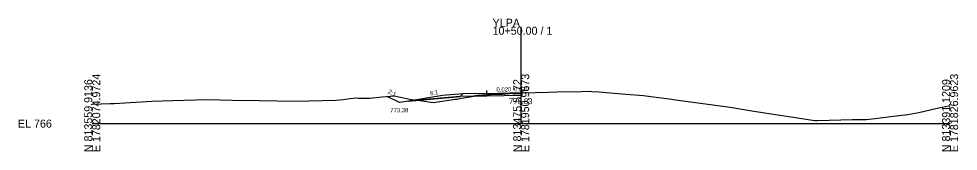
# Model space of a CAD drawing. Extents: x -76 to 1303, y -10 to 9544.
# Drawn here: x -25.7 to 302.8, y 490.3 to 536.8 of the extents above; entities that cross this region are included whole.
import ezdxf

# ---------------------------------------------------------------- set-up
doc = ezdxf.new("R2010")
doc.units = 0
for name, color, linetype in [('Exist Cross Section Cell', 7, 'Continuous'), ('Exist XS Center Line Elevation Label', 7, 'Continuous'), ('Exist XS Ground Line', 7, 'Continuous'), ('Prop XS Ditch Slope Text', 7, 'Continuous'), ('Prop XS Ditch Standard Text', 7, 'Continuous'), ('Prop XS Dump Level', 7, 'Continuous'), ('Prop XS Earthwork Shape', 7, 'Continuous'), ('Prop XS EOT Tick Mark', 7, 'Continuous'), ('Prop XS Finish Grade', 7, 'Continuous'), ('Prop XS Finish Grade Earthwork', 7, 'Continuous'), ('Prop XS Finish Grade Paved Shoulder', 7, 'Continuous'), ('Prop XS Finish Grade Pavement', 7, 'Continuous'), ('Prop XS Pvmt Edge Slope', 7, 'Continuous'), ('Prop XS SE Text', 7, 'Continuous'), ('Prop XS Side Slope Text', 7, 'Continuous'), ('Prop XS Subgrade Earthwork', 7, 'Continuous'), ('Scratch_Level_3', 7, 'Continuous')]:
    doc.layers.add(name, color=color, linetype=linetype)

msp = doc.modelspace()

# ---------------------------------------------------------------- linework, layer by layer
at = {"layer": 'Exist Cross Section Cell'}
for p, q in [((150, 500), (150, 533.98)), ((0, 500), (150, 500)), ((150, 500), (300, 500))]:
    msp.add_line(p, q, dxfattribs=at)
at = {"layer": 'Exist XS Ground Line'}
for p, q in [((97.02, 508.88), (101.39, 509.38)), ((101.39, 509.38), (105.59, 509.74)), ((105.59, 509.74), (110.49, 508.74)), ((128.56, 508.78), (134.87, 509.89)), ((134.87, 509.89), (136.31, 509.96)), ((136.31, 509.96), (140.75, 510.28)), ((140.75, 510.28), (143.54, 510.33)), ((143.54, 510.33), (146.83, 510.67)), ((146.83, 510.67), (147.68, 510.71)), ((147.68, 510.71), (150, 510.83)), ((150, 510.83), (150.34, 510.84)), ((150.34, 510.84), (159.59, 511.07)), ((159.59, 511.07), (162.62, 511.15)), ((162.62, 511.15), (171.12, 511.28)), ((171.12, 511.28), (173.88, 511.33)), ((173.88, 511.33), (174.73, 511.29)), ((174.73, 511.29), (177.16, 511.16)), ((177.16, 511.16), (186.58, 510.35)), ((186.58, 510.35), (192.75, 509.86)), ((192.75, 509.86), (195.3, 509.54)), ((195.3, 509.54), (202.66, 508.56)), ((0, 506.81), (6.24, 507.03)), ((6.24, 507.03), (7.7, 507.11)), ((7.7, 507.11), (20.79, 507.88)), ((20.79, 507.88), (28.23, 508.11)), ((28.23, 508.11), (36.13, 508.29)), ((36.13, 508.29), (40.4, 508.41)), ((40.4, 508.41), (49.08, 508.26)), ((49.08, 508.26), (58.35, 508.15)), ((58.35, 508.15), (70.93, 507.9)), ((70.93, 507.9), (85.2, 508.23)), ((85.2, 508.23), (87.79, 508.47)), ((87.79, 508.47), (90.16, 508.76)), ((90.16, 508.76), (91.2, 508.89)), ((91.2, 508.89), (91.98, 509)), ((91.98, 509), (92.99, 508.94)), ((92.99, 508.94), (97.02, 508.88)), ((110.49, 508.74), (113.07, 508.28)), ((113.07, 508.28), (114.61, 508.06)), ((114.61, 508.06), (119.24, 507.36)), ((119.24, 507.36), (127.07, 508.52)), ((127.07, 508.52), (127.66, 508.62)), ((127.66, 508.62), (128.56, 508.78)), ((202.66, 508.56), (203.1, 508.5)), ((203.1, 508.5), (223.11, 505.73)), ((295.47, 505.42), (300, 506.36)), ((223.11, 505.73), (231.33, 504.32)), ((231.33, 504.32), (252.74, 501.05)), ((280.07, 502.58), (285.2, 503.25)), ((285.2, 503.25), (289.04, 503.95)), ((289.04, 503.95), (295.47, 505.42)), ((252.74, 501.05), (253.66, 501.09)), ((253.66, 501.09), (265.92, 501.49)), ((265.92, 501.49), (270.61, 501.43)), ((270.61, 501.43), (273.8, 501.8)), ((273.8, 501.8), (280.07, 502.58))]:
    msp.add_line(p, q, dxfattribs=at)
at = {"layer": 'Prop XS Dump Level'}
for p, q in [((138, 510.62), (150, 510.86)), ((150, 510.86), (150.34, 510.87))]:
    msp.add_line(p, q, dxfattribs=at)
at = {"layer": 'Prop XS Earthwork Shape'}
for points in [[(113.77, 508.18), (110.54, 507.89), (107.47, 507.38), (103.17, 509.53), (105.59, 509.74), (110.49, 508.74), (113.07, 508.28)], [(113.77, 508.18), (114.61, 508.06), (119.24, 507.36), (127.07, 508.52), (127.66, 508.62), (128.56, 508.78), (133.26, 509.61), (128.71, 509.52)], [(150.02, 509.94), (150.34, 509.95), (150.34, 510.84), (150, 510.83), (147.68, 510.71), (146.83, 510.67), (143.54, 510.33), (140.75, 510.28), (136.31, 509.96), (134.87, 509.89), (133.26, 509.61), (138.02, 509.7)]]:
    msp.add_lwpolyline(points, close=True, dxfattribs=at)
at = {"layer": 'Prop XS EOT Tick Mark'}
for p, q in [((138, 510.62), (138, 511.62)), ((150.34, 510.87), (150.34, 511.87))]:
    msp.add_line(p, q, dxfattribs=at)
at = {"layer": 'Prop XS Finish Grade'}
for p, q in [((122.47, 509.88), (110.54, 507.89)), ((129.65, 510.45), (122.47, 509.88))]:
    msp.add_line(p, q, dxfattribs=at)
at = {"layer": 'Prop XS Finish Grade Earthwork'}
for p, q in [((107.47, 507.38), (103.17, 509.53)), ((110.54, 507.89), (107.47, 507.38))]:
    msp.add_line(p, q, dxfattribs=at)
at = {"layer": 'Prop XS Finish Grade Paved Shoulder'}
msp.add_line((138, 510.62), (129.65, 510.45), dxfattribs=at)
at = {"layer": 'Prop XS Finish Grade Pavement'}
for p, q in [((138, 510.62), (150, 510.86)), ((150, 510.86), (150.34, 510.87)), ((150.34, 510.87), (150.34, 510.84))]:
    msp.add_line(p, q, dxfattribs=at)
at = {"layer": 'Prop XS Pvmt Edge Slope'}
msp.add_line((129.65, 510.45), (128.71, 509.52), dxfattribs=at)
at = {"layer": 'Prop XS Subgrade Earthwork'}
for p, q in [((128.71, 509.52), (110.54, 507.89)), ((138.02, 509.7), (128.71, 509.52)), ((138.02, 509.7), (150.02, 509.94)), ((150.02, 509.94), (150.34, 509.95)), ((150.34, 509.95), (150.34, 510.84))]:
    msp.add_line(p, q, dxfattribs=at)
at = {"layer": 'Scratch_Level_3'}
for p, q in [((122.47, 509.88), (110.54, 507.89)), ((110.54, 507.89), (128.71, 509.52)), ((129.65, 510.45), (122.47, 509.88)), ((128.71, 509.52), (129.65, 510.45))]:
    msp.add_line(p, q, dxfattribs=at)

# ---------------------------------------------------------------- texts
at = {"layer": 'Exist Cross Section Cell'}
for s, p in [('YLPA', (140, 533.98)), ('10+50.00 / 1', (140, 531.18)), ('EL 766', (-26, 498.6))]:
    msp.add_text(s, height=2.8, dxfattribs=at).set_placement(p)
for s, p in [('E 1782074.9724', (2.8, 490)), ('E 1781950.9673', (152.8, 490)), ('E 1781826.9623', (302.8, 490)), ('N 813559.9136', (0, 490)), ('N 813475.5172', (150, 490)), ('N 813391.1209', (300, 490))]:
    msp.add_text(s, height=2.8, rotation=90, dxfattribs=at).set_placement(p)
at = {"layer": 'Exist XS Center Line Elevation Label'}
msp.add_text('776.83', height=2, dxfattribs=at).set_placement((145.75, 506.83))
at = {"layer": 'Prop XS Ditch Slope Text'}
msp.add_text('6:1', height=1.5, rotation=9.4623, dxfattribs=at).set_placement((118.25, 509.88))
at = {"layer": 'Prop XS Ditch Standard Text'}
msp.add_text('773.38', height=1.5, dxfattribs=at).set_placement((104.22, 503.98))
at = {"layer": 'Prop XS Dump Level'}
msp.add_text('Case4', height=0.04, dxfattribs=at).set_placement((122.47, 510.09))
at = {"layer": 'Prop XS SE Text'}
for rotation, p in [(1.1458, (141.38, 511.19)), (1.1457, (147.54, 511.31))]:
    msp.add_text('0.020', height=1.5, rotation=rotation, dxfattribs=at).set_placement(p)
at = {"layer": 'Prop XS Side Slope Text'}
msp.add_text('2:1', height=1.5, rotation=333.4349, dxfattribs=at).set_placement((103.25, 510.72))

doc.saveas('drawing.dxf')
